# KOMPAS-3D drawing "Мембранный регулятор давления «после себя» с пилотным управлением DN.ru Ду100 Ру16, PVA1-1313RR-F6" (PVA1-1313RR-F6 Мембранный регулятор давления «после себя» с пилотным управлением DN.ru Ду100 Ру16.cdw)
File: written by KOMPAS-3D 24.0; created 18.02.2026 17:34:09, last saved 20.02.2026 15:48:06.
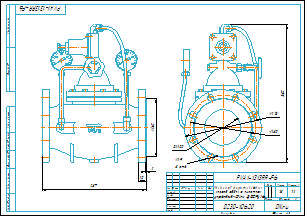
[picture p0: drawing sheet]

Document properties: art: D230-10620; Автор: R2D2; Форматы листов документа: A3; Полное имя файла: PVA1-1313RR-F Мембранный регулятор давления «после себя» с пилотным управлением DN.ru Ду100 Ру16.m3d; Масса: 18; Наименование: Мембранный регулятор давления «после себя» с пилотным управлением DN.ru Ду100 Ру16; Количество листов документа: 1; Примечание: D230-10620

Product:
- Part/product: Мембранный регулятор давления «после себя» с пилотным управлением DN.ru Ду100 Ру16  | designation PVA1-1313RR-F6
    Масса: 18
    Раздел спецификации: Прочие изделия
    Примечание: D230-10620
    additional columns: D230-10620

Referenced files in E:\Работа\Зайцев\Для компаса\: чертеж DN.ru А3.cdt
Referenced files in E:\Работа\Зайцев\PVA1-1313RR-F Мембранный регулятор давления «после себя» с пилотным управлением DN.ru Ду50-200 Ру16\DN100\: PVA1-1313RR-F Мембранный регулятор давления «после себя» с пилотным управлением DN.ru Ду100 Ру16.m3d
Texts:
  чертеж DN.ru А3.cdt
  Мембранный регулятор давления
  «после себя» с пилотным
  управлением DN.ru Ду100 Ру16
  PVA1-1313RR-F6
  prop
  Мембранный регулятор давления «после себя» с пилотным управлением DN.ru Ду100 Ру16
  PVA1-1313RR-F6 Мембранный регулятор давления «после себя» с пилотным управлением DN.ru Ду100 Ру16
Dimensions and other numbers on the sheet: 1:2; 0; 1; 2; 18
